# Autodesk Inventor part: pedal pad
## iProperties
Author: Administrator
Created: 2001-03
Part Number: pedal pad
Document SubType Name: Modeling
Designer: Administrator
Control State: 0
Master: False
Checked Out: False
PropertySet Name: Design Tracking Control
Shininess: 5.0
PropertySet Name: _Private Model Information
Density: 0.0
Volumn: 0.0
Area: 0.0
PropertySet Name: Model Information
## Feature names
1. Loft1
2. Extrusion1
3. Fillet1
4. Mirror1
5. Hole1
6. Extrusion2
7. Mirror2
8. Fillet2
9. Fillet3
10. Fillet4
